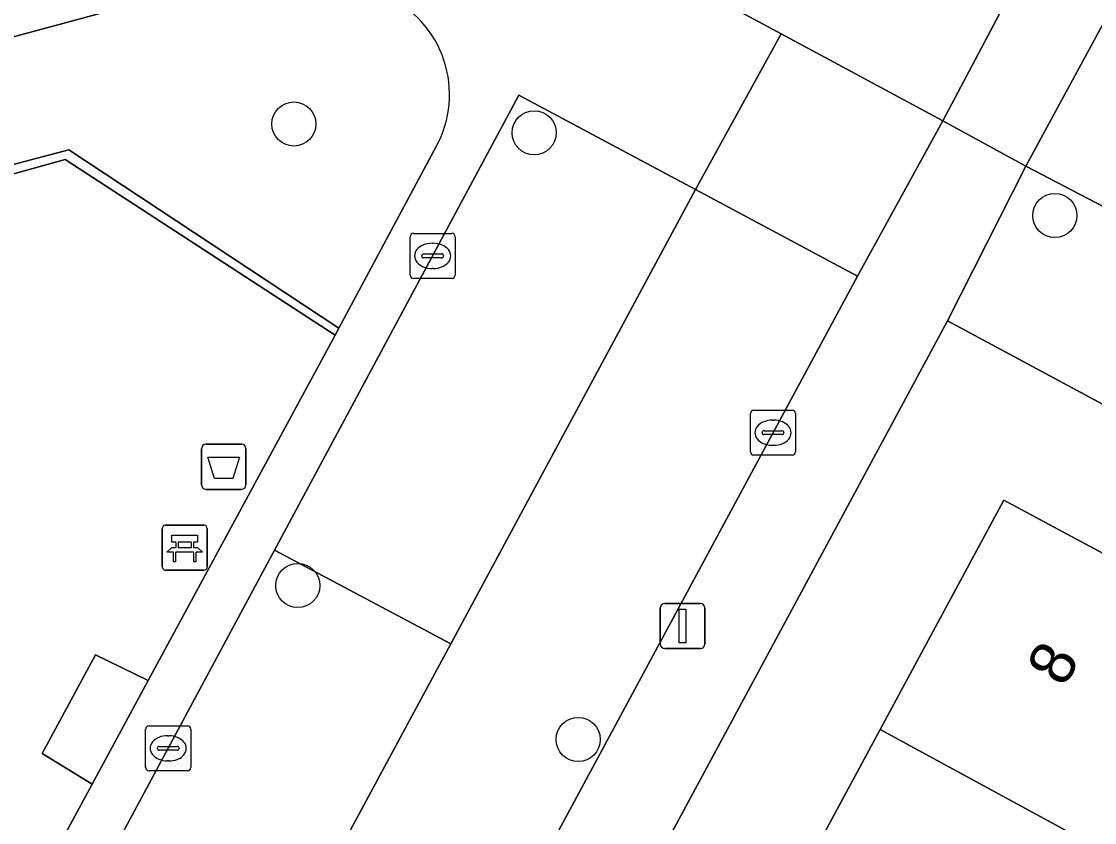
# Model space of a CAD drawing. Extents: x 159262 to 160143, y 383399 to 384319.
# Drawn here: x 159835.56 to 159859.37, y 383842.19 to 383859.96 of the extents above; entities that cross this region are included whole.
import ezdxf

# ---------------------------------------------------------------- set-up
doc = ezdxf.new("R2010")
doc.units = 0
for name, color, linetype in [('IMGEO_Afvalbak', 7, 'Continuous'), ('IMGEO_Bank', 7, 'Continuous'), ('IMGEO_Boom', 7, 'Continuous'), ('IMGEO_Erf', 7, 'Continuous'), ('IMGEO_Groenvoorziening', 7, 'Continuous'), ('IMGEO_Kolk', 7, 'Continuous'), ('IMGEO_Lichtmast', 7, 'Continuous'), ('IMGEO_Pand', 7, 'Continuous'), ('IMGEO_Pand_nummerreeks', 7, 'Continuous'), ('IMGEO_Parkeervlak_open', 7, 'Continuous'), ('IMGEO_Rijbaan_lokaal_open', 7, 'Continuous'), ('IMGEO_Terreindeel_open', 7, 'Continuous'), ('IMGEO_Terreindeel_zand', 7, 'Continuous'), ('IMGEO_Voetpad_open', 7, 'Continuous')]:
    doc.layers.add(name, color=color, linetype=linetype)

msp = doc.modelspace()

# ---------------------------------------------------------------- linework, layer by layer
at = {"layer": 'IMGEO_Afvalbak'}
for p, q in [((159839.653, 383850.583), (159840.443, 383850.583)), ((159840.443, 383850.583), (159839.653, 383850.583)), ((159839.553, 383849.683), (159839.553, 383850.483)), ((159839.553, 383850.483), (159839.553, 383849.683)), ((159840.543, 383850.483), (159840.543, 383849.683)), ((159840.543, 383849.683), (159840.543, 383850.483)), ((159840.443, 383849.583), (159839.653, 383849.583)), ((159839.653, 383849.583), (159840.443, 383849.583))]:
    msp.add_line(p, q, dxfattribs=at)
msp.add_lwpolyline([(159839.696, 383850.297), (159840.4, 383850.297), (159840.251, 383849.827), (159839.845, 383849.827), (159839.696, 383850.297)], dxfattribs=at)
for centre, start, end in [((159839.653, 383850.483), 90, 180), ((159839.653, 383850.483), 90, 180), ((159840.443, 383850.483), 0, 90), ((159840.443, 383850.483), 360, 90), ((159839.653, 383849.683), 180, 270), ((159839.653, 383849.683), 180, 270), ((159840.443, 383849.683), 270, 0), ((159840.443, 383849.683), 270, 0)]:
    msp.add_arc(centre, 0.1, start, end, dxfattribs=at)
at = {"layer": 'IMGEO_Bank'}
for p, q in [((159838.684, 383847.865), (159838.684, 383848.706)), ((159838.684, 383848.706), (159838.684, 383847.865)), ((159838.759, 383848.79), (159839.6, 383848.79)), ((159839.6, 383848.79), (159838.759, 383848.79)), ((159839.684, 383848.715), (159839.684, 383847.874)), ((159839.684, 383847.874), (159839.684, 383848.715)), ((159838.993, 383848.296), (159838.993, 383848.402)), ((159839.037, 383848.402), (159839.037, 383848.296)), ((159839.325, 383848.408), (159839.043, 383848.408)), ((159839.331, 383848.296), (159839.331, 383848.402)), ((159839.375, 383848.402), (159839.375, 383848.296)), ((159839.381, 383848.188), (159838.988, 383848.188)), ((159839.043, 383848.29), (159839.325, 383848.29)), ((159839.609, 383847.79), (159838.768, 383847.79)), ((159838.768, 383847.79), (159839.609, 383847.79))]:
    msp.add_line(p, q, dxfattribs=at)
for points in [[(159838.987, 383848.408), (159838.901, 383848.408), (159838.901, 383848.569), (159839.464, 383848.569), (159839.464, 383848.408), (159839.381, 383848.408)], [(159838.931, 383848.188), (159838.789, 383848.188), (159838.901, 383848.29), (159838.987, 383848.29)], [(159838.981, 383848.181), (159838.981, 383847.974), (159838.938, 383847.974), (159838.938, 383848.181)], [(159839.381, 383848.29), (159839.464, 383848.29), (159839.576, 383848.188), (159839.437, 383848.188)], [(159839.431, 383848.181), (159839.431, 383847.974), (159839.387, 383847.974), (159839.387, 383848.181)]]:
    msp.add_lwpolyline(points, dxfattribs=at)
for centre, radius, start, end in [((159838.762, 383848.712), 0.0779, 92.4484, 184.2845), ((159838.762, 383848.712), 0.0779, 92.4484, 184.2845), ((159839.606, 383848.712), 0.0779, 2.4484, 94.2845), ((159839.606, 383848.712), 0.0779, 2.4484, 94.2845), ((159838.986, 383848.401), 0.00671, 2.8957, 87.1043), ((159839.043, 383848.401), 0.00671, 92.8957, 177.1043), ((159839.325, 383848.401), 0.00671, 2.8957, 87.1043), ((159839.382, 383848.401), 0.00671, 92.8957, 177.1043), ((159838.931, 383848.181), 0.00671, 2.8957, 87.1043), ((159838.988, 383848.181), 0.00671, 92.8957, 177.1043), ((159838.986, 383848.297), 0.00671, 272.8957, 357.1043), ((159839.043, 383848.297), 0.00671, 182.8957, 267.1043), ((159839.325, 383848.297), 0.00671, 272.8957, 357.1043), ((159839.382, 383848.297), 0.00671, 182.8957, 267.1043), ((159839.38, 383848.181), 0.00671, 2.8957, 87.1043), ((159839.437, 383848.181), 0.00671, 92.8957, 177.1043), ((159838.762, 383847.868), 0.0779, 182.4484, 274.2845), ((159838.762, 383847.868), 0.0779, 182.4484, 274.2845), ((159839.606, 383847.868), 0.0779, 272.4484, 4.2845), ((159839.606, 383847.868), 0.0779, 272.4484, 4.2845)]:
    msp.add_arc(centre, radius, start, end, dxfattribs=at)
at = {"layer": 'IMGEO_Boom'}
for centre in [(159841.606, 383857.686), (159846.937, 383857.492), (159858.488, 383855.656), (159841.691, 383847.449), (159847.914, 383844.037)]:
    msp.add_circle(centre, 0.489, dxfattribs=at)
at = {"layer": 'IMGEO_Erf'}
msp.add_lwpolyline([(159882.827, 383838.967), (159856.103, 383853.317), (159839.043, 383821.661), (159826.175, 383818.139), (159825.07, 383817.837), (159832.903, 383788.947), (159833.158, 383789.017), (159832.573, 383791.181), (159835.671, 383792.017), (159836.255, 383789.853), (159836.757, 383789.988), (159835.835, 383793.404), (159840.442, 383794.663), (159840.765, 383793.48), (159846.59, 383795.072), (159847.208, 383792.81), (159859.628, 383796.267), (159860.523, 383796.509)], close=True, dxfattribs=at)
msp.add_lwpolyline([(159841.055, 383819.128), (159843.839, 383824.287), (159846.533, 383829.279), (159849.227, 383834.272), (159851.921, 383839.265), (159854.615, 383844.258), (159857.358, 383849.341), (159864.778, 383845.357)], dxfattribs=at)
at = {"layer": 'IMGEO_Groenvoorziening'}
msp.add_lwpolyline([(159841.219, 383861.2), (159834.414, 383859.358), (159835.1, 383856.714), (159836.609, 383857.111), (159842.605, 383853.16), (159844.765, 383857.184)], dxfattribs=at)
msp.add_arc((159842.65, 383858.338), 2.409, 331.3871, 65.5855, dxfattribs=at)
at = {"layer": 'IMGEO_Kolk'}
for p, q in [((159844.259, 383855.261), (159845.111, 383855.261)), ((159844.184, 383854.335), (159844.184, 383855.187)), ((159844.672, 383855.041), (159844.697, 383855.041)), ((159845.185, 383855.187), (159845.185, 383854.335)), ((159844.486, 383854.804), (159844.884, 383854.804)), ((159844.443, 383854.755), (159844.443, 383854.767)), ((159844.881, 383854.718), (159844.483, 383854.718)), ((159844.927, 383854.767), (159844.927, 383854.755)), ((159844.695, 383854.481), (159844.67, 383854.481)), ((159845.111, 383854.261), (159844.259, 383854.261)), ((159851.734, 383850.413), (159851.734, 383851.265)), ((159851.809, 383851.339), (159852.661, 383851.339)), ((159852.735, 383851.265), (159852.735, 383850.413)), ((159852.222, 383851.119), (159852.247, 383851.119)), ((159851.993, 383850.833), (159851.993, 383850.845)), ((159852.431, 383850.796), (159852.033, 383850.796)), ((159852.036, 383850.882), (159852.434, 383850.882)), ((159852.477, 383850.845), (159852.477, 383850.833)), ((159852.245, 383850.559), (159852.22, 383850.559)), ((159852.661, 383850.339), (159851.809, 383850.339)), ((159838.392, 383844.339), (159839.244, 383844.339)), ((159838.317, 383843.413), (159838.317, 383844.265)), ((159838.805, 383844.119), (159838.83, 383844.119)), ((159839.318, 383844.265), (159839.318, 383843.413)), ((159838.576, 383843.833), (159838.576, 383843.845)), ((159838.619, 383843.882), (159839.017, 383843.882)), ((159839.06, 383843.845), (159839.06, 383843.833)), ((159839.014, 383843.796), (159838.616, 383843.796)), ((159838.828, 383843.559), (159838.803, 383843.559)), ((159839.244, 383843.339), (159838.392, 383843.339))]:
    msp.add_line(p, q, dxfattribs=at)
for points in [[(159844.259, 383855.261), (159845.111, 383855.261)], [(159844.184, 383854.335), (159844.184, 383855.187)], [(159845.185, 383855.187), (159845.185, 383854.335)], [(159845.111, 383854.261), (159844.259, 383854.261)], [(159851.734, 383850.413), (159851.734, 383851.265)], [(159851.809, 383851.339), (159852.661, 383851.339)], [(159852.735, 383851.265), (159852.735, 383850.413)], [(159852.661, 383850.339), (159851.809, 383850.339)], [(159838.392, 383844.339), (159839.244, 383844.339)], [(159838.317, 383843.413), (159838.317, 383844.265)], [(159839.318, 383844.265), (159839.318, 383843.413)], [(159839.244, 383843.339), (159838.392, 383843.339)]]:
    msp.add_lwpolyline(points, dxfattribs=at)
for centre, radius, start, end in [((159844.261, 383855.185), 0.0765, 91.552, 178.448), ((159844.261, 383855.185), 0.0765, 91.552, 178.448), ((159845.109, 383855.185), 0.0765, 1.552, 88.448), ((159845.109, 383855.185), 0.0765, 1.552, 88.448), ((159844.483, 383854.764), 0.0403, 85.8775, 175.7526), ((159844.888, 383854.766), 0.0386, 1.7309, 96.639), ((159844.48, 383854.754), 0.0366, 178.938, 274.7102), ((159844.884, 383854.761), 0.043, 264.8664, 352.4533), ((159844.261, 383854.337), 0.0765, 181.552, 268.448), ((159844.261, 383854.337), 0.0765, 181.552, 268.448), ((159845.109, 383854.337), 0.0765, 271.552, 358.448), ((159845.109, 383854.337), 0.0765, 271.552, 358.448), ((159851.811, 383851.263), 0.0765, 91.552, 178.448), ((159851.811, 383851.263), 0.0765, 91.552, 178.448), ((159852.659, 383851.263), 0.0765, 1.552, 88.448), ((159852.659, 383851.263), 0.0765, 1.552, 88.448), ((159852.033, 383850.842), 0.0403, 85.8775, 175.7526), ((159852.03, 383850.832), 0.0366, 178.938, 274.7102), ((159852.434, 383850.839), 0.043, 264.8664, 352.4533), ((159852.438, 383850.844), 0.0386, 1.7309, 96.639), ((159851.811, 383850.415), 0.0765, 181.552, 268.448), ((159851.811, 383850.415), 0.0765, 181.552, 268.448), ((159852.659, 383850.415), 0.0765, 271.552, 358.448), ((159852.659, 383850.415), 0.0765, 271.552, 358.448), ((159838.394, 383844.263), 0.0765, 91.552, 178.448), ((159838.394, 383844.263), 0.0765, 91.552, 178.448), ((159839.242, 383844.263), 0.0765, 1.552, 88.448), ((159839.242, 383844.263), 0.0765, 1.552, 88.448), ((159838.616, 383843.842), 0.0403, 85.8775, 175.7526), ((159838.613, 383843.832), 0.0366, 178.938, 274.7102), ((159839.017, 383843.839), 0.043, 264.8664, 352.4533), ((159839.021, 383843.844), 0.0386, 1.7309, 96.639), ((159838.394, 383843.415), 0.0765, 181.552, 268.448), ((159838.394, 383843.415), 0.0765, 181.552, 268.448), ((159839.242, 383843.415), 0.0765, 271.552, 358.448), ((159839.242, 383843.415), 0.0765, 271.552, 358.448)]:
    msp.add_arc(centre, radius, start, end, dxfattribs=at)
for centre, major_axis, ratio, start_param, end_param in [((159844.671, 383854.761), (-0.387, 0.002), 0.722429, 4.712389, 7.853982), ((159844.696, 383854.761), (-0.39, 0.002), 0.717154, 1.570796, 4.712389), ((159852.221, 383850.839), (-0.387, 0.002), 0.722429, 4.712389, 7.853982), ((159852.246, 383850.839), (-0.39, 0.002), 0.717154, 1.570796, 4.712389), ((159838.804, 383843.839), (-0.387, 0.002), 0.722429, 4.712389, 7.853982), ((159838.829, 383843.839), (-0.39, 0.002), 0.717154, 1.570796, 4.712389)]:
    msp.add_ellipse(centre, major_axis=major_axis, ratio=ratio, start_param=start_param, end_param=end_param, dxfattribs=at)
at = {"layer": 'IMGEO_Lichtmast'}
for p, q in [((159849.734, 383846.153), (159849.734, 383846.953)), ((159849.734, 383846.953), (159849.734, 383846.153)), ((159849.834, 383847.053), (159850.624, 383847.053)), ((159850.624, 383847.053), (159849.834, 383847.053)), ((159850.724, 383846.953), (159850.724, 383846.153)), ((159850.724, 383846.153), (159850.724, 383846.953)), ((159850.624, 383846.053), (159849.834, 383846.053)), ((159849.834, 383846.053), (159850.624, 383846.053))]:
    msp.add_line(p, q, dxfattribs=at)
msp.add_lwpolyline([(159850.154, 383846.928), (159850.304, 383846.928), (159850.304, 383846.178), (159850.154, 383846.178), (159850.154, 383846.928)], dxfattribs=at)
for centre, start, end in [((159849.834, 383846.953), 90, 180), ((159849.834, 383846.953), 90, 180), ((159850.624, 383846.953), 0, 90), ((159850.624, 383846.953), 360, 90), ((159849.834, 383846.153), 180, 270), ((159849.834, 383846.153), 180, 270), ((159850.624, 383846.153), 270, 0), ((159850.624, 383846.153), 270, 0)]:
    msp.add_arc(centre, 0.1, start, end, dxfattribs=at)
at = {"layer": 'IMGEO_Pand'}
for points in [[(159863.539, 383843.041), (159864.778, 383845.357), (159857.358, 383849.341), (159854.615, 383844.258), (159868.067, 383836.942), (159869.595, 383839.774)], [(159854.615, 383844.258), (159851.921, 383839.265), (159859.328, 383835.235), (159860.511, 383837.428), (159866.566, 383834.16), (159867.221, 383835.374), (159868.067, 383836.942)]]:
    msp.add_lwpolyline(points, close=True, dxfattribs=at)
at = {"layer": 'IMGEO_Parkeervlak_open'}
for points in [[(159841.179, 383848.236), (159845.087, 383846.16), (159850.517, 383856.232), (159846.598, 383858.324)], [(159836.244, 383839.05), (159840.11, 383836.928), (159845.087, 383846.16), (159841.179, 383848.236)]]:
    msp.add_lwpolyline(points, close=True, dxfattribs=at)
at = {"layer": 'IMGEO_Rijbaan_lokaal_open'}
for points in [[(159829.067, 383858.936), (159845.486, 383863.41), (159852.414, 383859.686), (159856.001, 383857.758), (159858.117, 383861.754), (159846.081, 383868.251), (159827.864, 383863.295)], [(159860.012, 383860.749), (159858.117, 383861.754), (159856.001, 383857.758), (159857.844, 383856.752)], [(159886.416, 383846.531), (159862.1, 383859.594), (159860.012, 383860.749), (159857.844, 383856.752), (159859.758, 383855.756), (159884.147, 383842.627)], [(159854.11, 383854.314), (159856.001, 383857.758), (159852.414, 383859.686), (159850.517, 383856.232)], [(159832.331, 383825.901), (159822.082, 383823.083), (159823.001, 383819.628), (159824.545, 383820.045), (159837.523, 383823.55), (159854.11, 383854.314), (159850.517, 383856.232), (159845.087, 383846.16), (159840.11, 383836.928), (159835.147, 383827.758), (159834.459, 383826.486)]]:
    msp.add_lwpolyline(points, close=True, dxfattribs=at)
at = {"layer": 'IMGEO_Terreindeel_open'}
msp.add_lwpolyline([(159837.128, 383843.044), (159838.374, 383845.345), (159837.205, 383845.912), (159836.023, 383843.727)], close=True, dxfattribs=at)
at = {"layer": 'IMGEO_Terreindeel_zand'}
msp.add_lwpolyline([(159828.975, 383840.594), (159831.532, 383846.136), (159830.58, 383849.746), (159832.31, 383850.222), (159830.972, 383855.356), (159836.528, 383856.898), (159842.519, 383852.999), (159842.605, 383853.16), (159836.609, 383857.111), (159835.1, 383856.714), (159819.695, 383852.659), (159817.412, 383852.058), (159823.007, 383831.376), (159832.16, 383833.878), (159832.236, 383834.018), (159830.889, 383833.695)], close=True, dxfattribs=at)
at = {"layer": 'IMGEO_Voetpad_open'}
for points in [[(159820.298, 383830.529), (159820.428, 383829.823), (159820.938, 383827.383), (159831.484, 383830.189), (159836.244, 383839.05), (159841.179, 383848.236), (159846.598, 383858.324), (159850.517, 383856.232), (159852.414, 383859.686), (159845.486, 383863.41)], [(159845.486, 383863.41), (159829.067, 383858.936), (159828.046, 383858.656), (159828.31, 383857.705), (159829.332, 383857.982), (159834.414, 383859.358), (159841.219, 383861.2)], [(159844.765, 383857.184), (159842.605, 383853.16), (159842.519, 383852.999), (159838.374, 383845.345), (159837.128, 383843.044), (159832.236, 383834.018), (159832.16, 383833.878), (159830.912, 383831.586)], [(159859.758, 383855.756), (159857.844, 383856.752), (159856.103, 383853.317), (159882.827, 383838.967), (159884.237, 383838.21), (159889.412, 383835.428), (159894.429, 383832.73), (159899.446, 383830.033), (159904.462, 383827.336), (159909.479, 383824.639), (159914.461, 383821.96), (159917.055, 383820.574), (159917.816, 383822.24), (159912.321, 383825.347), (159912.378, 383825.451), (159888.497, 383838.27)]]:
    msp.add_lwpolyline(points, dxfattribs=at)
for points in [[(159856.103, 383853.317), (159857.844, 383856.752), (159856.001, 383857.758), (159854.11, 383854.314), (159837.523, 383823.55), (159824.545, 383820.045), (159825.07, 383817.837), (159826.175, 383818.139), (159839.043, 383821.661)], [(159832.236, 383834.018), (159837.128, 383843.044), (159836.023, 383843.727), (159837.205, 383845.912), (159838.374, 383845.345), (159842.519, 383852.999), (159836.528, 383856.898), (159830.972, 383855.356), (159832.31, 383850.222), (159830.58, 383849.746), (159831.532, 383846.136), (159828.975, 383840.594), (159830.889, 383833.695)]]:
    msp.add_lwpolyline(points, close=True, dxfattribs=at)
msp.add_arc((159842.65, 383858.338), 2.409, 331.3871, 65.5855, dxfattribs=at)

# ---------------------------------------------------------------- texts
at = {"layer": 'IMGEO_Pand_nummerreeks'}
msp.add_text('8', height=1, rotation=61.6445, dxfattribs=at).set_placement((159858.702, 383845.168))

doc.saveas('drawing.dxf')
